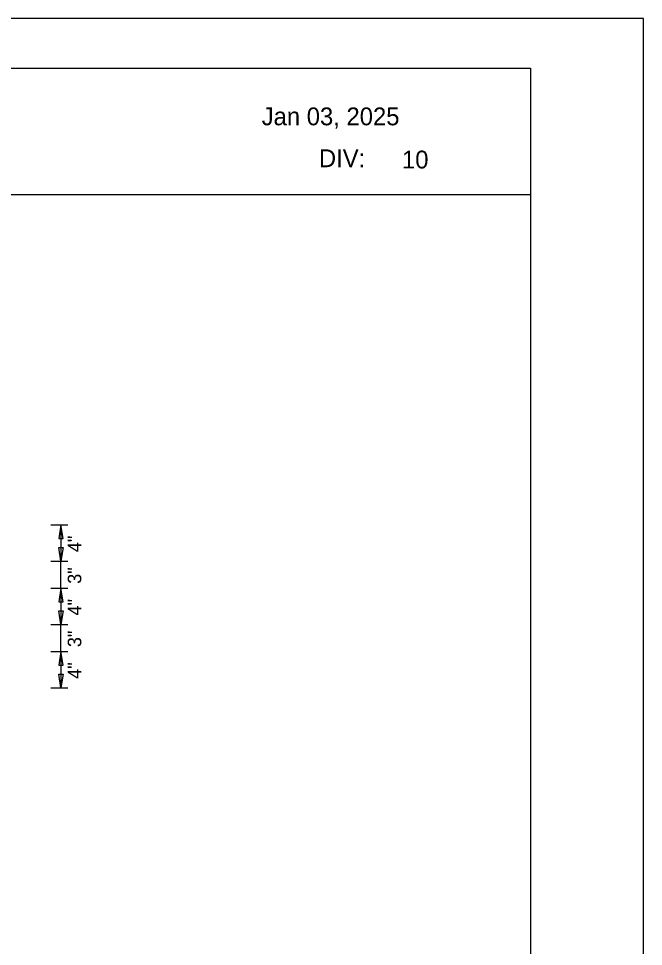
# Model space of a CAD drawing. Extents: x 1788.1 to 1851.2, y 237.2 to 283.4.
# Drawn here: x 1811.36 to 1818.27, y 273.15 to 283.41 of the extents above; entities that cross this region are included whole.
import ezdxf

# ---------------------------------------------------------------- set-up
doc = ezdxf.new("R2010")
doc.units = 0
for name, color, linetype in [('GSDIMS', 7, 'Continuous'), ('Old_Level_2', 7, 'Continuous'), ('Old_Level_3', 7, 'Continuous'), ('Sheet Plot Border Outside CELL', 7, 'Continuous')]:
    doc.layers.add(name, color=color, linetype=linetype)

msp = doc.modelspace()

# ---------------------------------------------------------------- linework, layer by layer
at = {"layer": 'GSDIMS'}
for p, q in [((1811.72, 277.81), (1811.908, 277.81)), ((1811.72, 277.81), (1811.908, 277.81)), ((1811.833, 277.81), (1811.833, 277.41)), ((1811.72, 277.41), (1811.908, 277.41)), ((1811.72, 277.41), (1811.908, 277.41)), ((1811.833, 277.11), (1811.833, 277.41)), ((1811.72, 277.11), (1811.908, 277.11)), ((1811.72, 277.11), (1811.908, 277.11)), ((1811.833, 277.11), (1811.833, 276.71)), ((1811.72, 276.71), (1811.908, 276.71)), ((1811.72, 276.71), (1811.908, 276.71)), ((1811.833, 276.41), (1811.833, 276.71)), ((1811.72, 276.41), (1811.908, 276.41)), ((1811.72, 276.41), (1811.908, 276.41)), ((1811.833, 276.41), (1811.833, 276.01)), ((1811.72, 276.01), (1811.908, 276.01)), ((1811.72, 276.01), (1811.908, 276.01))]:
    msp.add_line(p, q, dxfattribs=at)
for points in [[(1811.833, 277.81), (1811.808, 277.66), (1811.858, 277.66)], [(1811.833, 277.41), (1811.808, 277.56), (1811.858, 277.56)], [(1811.833, 277.11), (1811.808, 276.96), (1811.858, 276.96)], [(1811.833, 276.71), (1811.808, 276.86), (1811.858, 276.86)], [(1811.833, 276.41), (1811.808, 276.26), (1811.858, 276.26)], [(1811.833, 276.01), (1811.808, 276.16), (1811.858, 276.16)]]:
    msp.add_lwpolyline(points, close=True, dxfattribs=at)
at = {"layer": 'Old_Level_2'}
msp.add_line((1799.855, 281.461), (1817.019, 281.461), dxfattribs=at)
msp.add_lwpolyline([(1788.693, 282.859), (1817.019, 282.859), (1817.019, 263.214), (1788.693, 263.214)], close=True, dxfattribs=at)
at = {"layer": 'Sheet Plot Border Outside CELL'}
msp.add_lwpolyline([(1818.269, 283.406), (1788.097, 283.406), (1788.097, 262.552), (1818.269, 262.552)], close=True, dxfattribs=at)

# ---------------------------------------------------------------- texts
at = {"layer": 'GSDIMS'}
for s, p in [('4"', (1812.058, 277.508)), ('3"', (1812.058, 277.158)), ('4"', (1812.058, 276.808)), ('3"', (1812.058, 276.458)), ('4"', (1812.058, 276.108))]:
    msp.add_text(s, height=0.15, rotation=90, dxfattribs=at).set_placement(p)
at = {"layer": 'Old_Level_2'}
for s, p in [('DIV:', (1814.683, 281.763)), ('10', (1815.601, 281.749))]:
    msp.add_text(s, height=0.1969, rotation=360, dxfattribs=at).set_placement(p)
at = {"layer": 'Old_Level_3'}
msp.add_text('Jan 03, 2025', height=0.19685, dxfattribs=at).set_placement((1814.051, 282.226))

doc.saveas('drawing.dxf')
